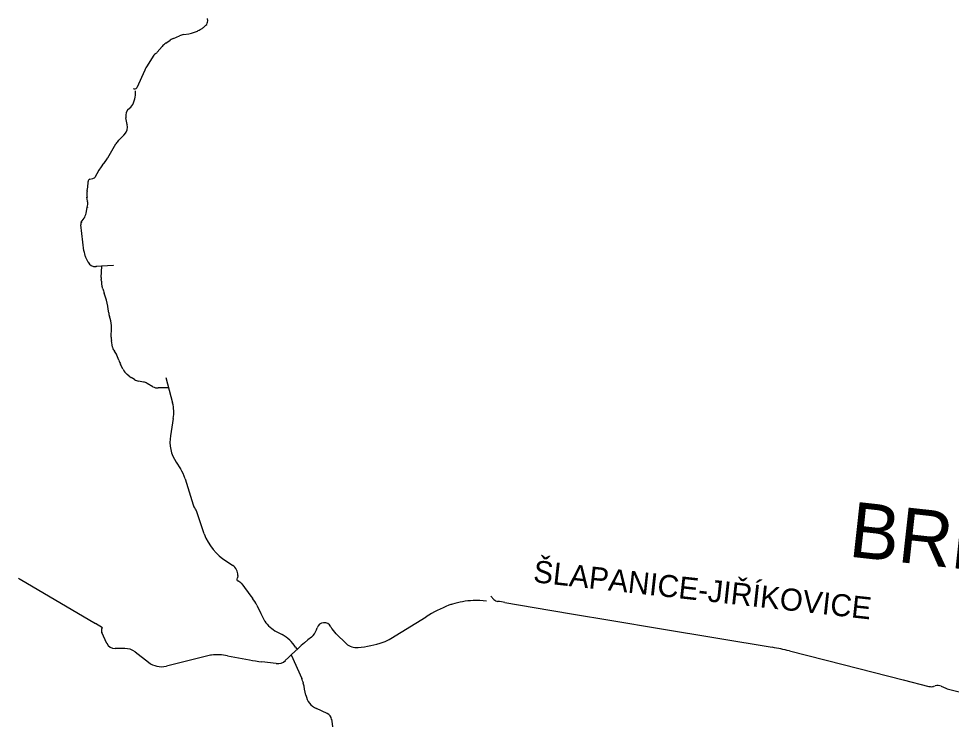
# Model space of a CAD drawing. Extents: x -678204 to -526855, y -1228851 to -1110393.
# Drawn here: x -590464 to -587930, y -1165121 to -1163218 of the extents above; entities that cross this region are included whole.
import ezdxf

# ---------------------------------------------------------------- set-up
doc = ezdxf.new("R2010")
doc.units = 0
for name, color, linetype in [('00_n_cyklo popisy detaily', 7, 'Continuous'), ('00_n_cyklo popisy ostatni', 7, 'Continuous'), ('00_n_cyklo realizace rekreacni vedlejsi', 7, 'Continuous'), ('00_n_cyklo studie rekreacni vedlejsi', 7, 'Continuous'), ('00_n_cyklo trasovani rekreacni vedlejsi', 7, 'Continuous')]:
    doc.layers.add(name, color=color, linetype=linetype)

msp = doc.modelspace()

# ---------------------------------------------------------------- linework, layer by layer
at = {"layer": '00_n_cyklo realizace rekreacni vedlejsi'}
for p, q in [((-590146.2, -1163416.5), (-590146.4, -1163413.8)), ((-590151.8, -1163446.5), (-590148.4, -1163435.5)), ((-590162.9, -1163461.8), (-590162.6, -1163461.6)), ((-590168.7, -1163505), (-590172.5, -1163487.1)), ((-590192.6, -1163548.5), (-590176.7, -1163532.2)), ((-590222, -1163595.9), (-590200, -1163558.2)), ((-590237.2, -1163616.9), (-590229.2, -1163606.4)), ((-590254.8, -1163646.5), (-590245.7, -1163629.9)), ((-590270.6, -1163654.3), (-590262.6, -1163652.4)), ((-590275.4, -1163666.7), (-590275.2, -1163660)), ((-590276.7, -1163713.3), (-590278.2, -1163703.2)), ((-590277.7, -1163685.9), (-590277.4, -1163684.4)), ((-590280.7, -1163746.5), (-590277.3, -1163731.2)), ((-590293.6, -1163771), (-590286.3, -1163759.9)), ((-590286.7, -1163848.9), (-590295.2, -1163777.7)), ((-590275.3, -1163878.9), (-590282.1, -1163864.6)), ((-590207.1, -1163887.9), (-590253.8, -1163891.4)), ((-590239.5, -1163921.3), (-590238.2, -1163890.2)), ((-590235.3, -1163951.4), (-590236.7, -1163945.2)), ((-590228.1, -1163974.1), (-590231.9, -1163963.5)), ((-590080, -1164220.5), (-590084.7, -1164220.9)), ((-590056.5, -1164220.8), (-590075.2, -1164220.4)), ((-589181.2, -1164786.7), (-589172.8, -1164795)), ((-589015.6, -1164825.3), (-588956.2, -1164835.4)), ((-588956.2, -1164835.4), (-588857.2, -1164851.5)), ((-588857.2, -1164851.5), (-588716.9, -1164874.7)), ((-588716.9, -1164874.7), (-588416.4, -1164925.2)), ((-588369.7, -1164934.9), (-588223.5, -1164971.5)), ((-588223.5, -1164971.5), (-588060.8, -1165013.5)), ((-588060.8, -1165013.5), (-587990.9, -1165031.3)), ((-587977.8, -1165031.1), (-587973.7, -1165029.9)), ((-587957.1, -1165030.9), (-587944.7, -1165036.2)), ((-587937.5, -1165038.6), (-587886.8, -1165051.5))]:
    msp.add_line(p, q, dxfattribs=at)
for points in [[(-590239.1, -1163930.6), (-590239.4, -1163926.5)], [(-590236.7, -1163945.2), (-590238.3, -1163937.2)], [(-590219.3, -1164017.1), (-590220.5, -1164006.7)], [(-590215.4, -1164032.3), (-590217.4, -1164026)], [(-590212.3, -1164082.5), (-590211.9, -1164057.4)], [(-590208.7, -1164110.3), (-590211.7, -1164091.6)], [(-590192, -1164145.2), (-590196.9, -1164131.6)], [(-590180.4, -1164170.1), (-590187.2, -1164156.5)], [(-590163.6, -1164188.8), (-590168.8, -1164184.6)], [(-590149.4, -1164198.3), (-590158.4, -1164192.6)], [(-590124.8, -1164204.8), (-590138.5, -1164202.4)], [(-590099.2, -1164217.5), (-590114.6, -1164208.5)], [(-589142.8, -1164803.6), (-589062.9, -1164817.4), (-589015.6, -1164825.3)]]:
    msp.add_lwpolyline(points, dxfattribs=at)
for centre in [(-590146.4, -1163413.8), (-590146.2, -1163416.5), (-590151.8, -1163446.5), (-590148.4, -1163435.5), (-590162.9, -1163461.8), (-590162.6, -1163461.6), (-590172.5, -1163487.1), (-590168.7, -1163505), (-590176.7, -1163532.2), (-590192.6, -1163548.5), (-590200, -1163558.2), (-590229.2, -1163606.4), (-590222, -1163595.9), (-590245.7, -1163629.9), (-590237.2, -1163616.9), (-590270.6, -1163654.3), (-590262.6, -1163652.4), (-590254.8, -1163646.5), (-590277.4, -1163684.4), (-590275.4, -1163666.7), (-590275.2, -1163660), (-590278.2, -1163703.2), (-590277.7, -1163685.9), (-590277.3, -1163731.2), (-590276.7, -1163713.3), (-590286.3, -1163759.9), (-590280.7, -1163746.5), (-590295.2, -1163777.7), (-590293.6, -1163771), (-590286.7, -1163848.9), (-590282.1, -1163864.6), (-590275.3, -1163878.9), (-590253.8, -1163891.4), (-590207.1, -1163887.9)]:
    msp.add_circle(centre, 0.15, dxfattribs=at)
for centre, radius, start, end in [((-590196, -1163420.4), 50, 342.4243, 4.5169), ((-590180.4, -1163437.4), 30, 306.4827, 342.4243), ((-590148.1, -1163481.9), 25, 126.4827, 191.9577), ((-590198.1, -1163511.2), 30, 315.5835, 11.9577), ((-590156.9, -1163583.4), 50, 135.5835, 149.6921), ((-590308.4, -1163545.4), 100, 322.3836, 329.6921), ((-590158, -1163677.9), 100, 142.3836, 151.2999), ((-590269.2, -1163660.1), 6, 103.1003, 178.6386), ((-590265.3, -1163640.7), 12, 283.1003, 331.2999), ((-590375.3, -1163664.3), 100, 348.4019, 358.6386), ((-590228.7, -1163696), 50, 168.4019, 188.347), ((-590326.2, -1163720.5), 50, 347.6706, 8.347), ((-590319.8, -1163738), 40, 326.7073, 347.6706), ((-590285.2, -1163776.5), 10, 146.7073, 186.7683), ((-590237, -1163843), 50, 186.7683, 205.6134), ((-590255.4, -1163869.4), 22, 205.6134, 274.1809), ((-590189.5, -1163923.3), 50, 177.6309, 183.6765), ((-590189.3, -1163927.4), 50, 183.6765, 191.2478), ((-590137.6, -1163930), 100, 192.3715, 199.5404), ((-590369.5, -1164024.3), 150, 6.7408, 19.5404), ((-590169.6, -1164011.2), 50, 186.7408, 197.1797), ((-590291.9, -1164055.9), 80, 358.9569, 17.1797), ((-590162.4, -1164083.4), 50, 178.9569, 189.4805), ((-590189, -1164107.2), 20, 188.9564, 223.6965), ((-590225.1, -1164141.7), 30, 19.6706, 43.6965), ((-590097.8, -1164111.6), 100, 199.6706, 206.6907), ((-590140.1, -1164149.9), 45, 206.6907, 230.4758), ((-590131.8, -1164150.3), 50, 230.4758, 237.866), ((-590133.4, -1164172.9), 30, 237.866, 260.3649), ((-590129.8, -1164234.3), 30, 59.6272, 80.3649), ((-590086.6, -1164195.9), 25, 239.6272, 274.3125), ((-590076.3, -1164270.4), 50, 88.7974, 94.3125), ((-589158.8, -1164780.7), 20, 225.5225, 260.9876), ((-589379.8, -1166174.2), 1391, 80.1867, 80.9876), ((-588516.4, -1165521.1), 604.3, 75.9478, 80.4704), ((-587984.7, -1165007.1), 25, 255.7386, 285.9313), ((-587966.8, -1165054), 25, 67.0256, 105.9313), ((-587925.2, -1164990.2), 50, 247.0256, 255.7206)]:
    msp.add_arc(centre, radius, start, end, dxfattribs=at)
at = {"layer": '00_n_cyklo studie rekreacni vedlejsi'}
for p, q in [((-590098.4, -1163320), (-590114.9, -1163345.9)), ((-590121.4, -1163357.9), (-590143.2, -1163405.6)), ((-590063.8, -1164192.7), (-590045.7, -1164261.7)), ((-590043.8, -1164303.6), (-590051.6, -1164350.5)), ((-590035.9, -1164422.7), (-590024.3, -1164440.1)), ((-590011.5, -1164467.2), (-589990.1, -1164538.6)), ((-589959.6, -1164617.3), (-589979.5, -1164557.2)), ((-589898.9, -1164691.5), (-589882.1, -1164702.6)), ((-590459.5, -1164740.4), (-590254.9, -1164860.8)), ((-589868.8, -1164729.9), (-589869.2, -1164736.1)), ((-589452.2, -1164901.2), (-589356.6, -1164842)), ((-589654.6, -1164877.6), (-589652.8, -1164872)), ((-590224.6, -1164914.4), (-590238, -1164884.8)), ((-589601.6, -1164888.7), (-589573.6, -1164915.2)), ((-590175.6, -1164928.3), (-590201.6, -1164928.7)), ((-590147.3, -1164937.8), (-590111.4, -1164965.8)), ((-589946.5, -1164947.4), (-590062.6, -1164976.2)), ((-589896.4, -1164948.1), (-589836.9, -1164959.4)), ((-589723.7, -1164945.7), (-589694.8, -1165009.8)), ((-589763.9, -1164969.4), (-589802.9, -1164964.7)), ((-589625.2, -1165105.1), (-589654.9, -1165091.7)), ((-589613.6, -1165120.7), (-589602.2, -1165208.7))]:
    msp.add_line(p, q, dxfattribs=at)
for points in [[(-589950.2, -1163224.2), (-589950.5, -1163218)], [(-589993.9, -1163257), (-589981, -1163252.8)], [(-589970.6, -1163247.9), (-589967.1, -1163245.7)], [(-589959.7, -1163240.2), (-589955.1, -1163236)], [(-590064.1, -1163284.7), (-590052, -1163276.4)], [(-590043.5, -1163271.7), (-590026.9, -1163264.6)], [(-590015.3, -1163261.2), (-590001.6, -1163258.9)], [(-590087.1, -1163309.1), (-590074, -1163293.6)], [(-589870.5, -1164744.1), (-589868.8, -1164744.8)], [(-589857.8, -1164753.1), (-589832.9, -1164786), (-589828.7, -1164791.3)], [(-589817, -1164810.4), (-589806.2, -1164833.6), (-589796.1, -1164853.2), (-589795.4, -1164854.2)], [(-590236.4, -1164872.4), (-590254.9, -1164860.8)], [(-590237.5, -1164874), (-590236.6, -1164872.4)], [(-589762.7, -1164882.7), (-589747.8, -1164890.8)], [(-589711.5, -1164924.6), (-589707.4, -1164930.9)]]:
    msp.add_lwpolyline(points, dxfattribs=at)
for centre, radius, start, end in [((-589965.2, -1163224.9), 15, 312.1361, 2.6801), ((-589996.9, -1163205.3), 50, 288.4339, 301.6564), ((-589993.3, -1163203.1), 50, 301.6564, 312.1361), ((-590023.7, -1163317.6), 50, 113.2231, 124.4406), ((-590007.2, -1163310.5), 50, 99.2944, 113.2231), ((-590009.7, -1163209.6), 50, 279.2944, 288.4339), ((-590035.8, -1163325.9), 50, 124.4406, 139.8304), ((-590077.3, -1163333.3), 25, 120.6685, 147.6354), ((-590077.3, -1163333.3), 25, 120.6685, 147.6354), ((-590095.2, -1163303.2), 10, 300.6685, 323.9419), ((-590095.2, -1163303.2), 10, 300.6685, 323.9419), ((-590030.4, -1163399.5), 100, 147.6354, 155.4273), ((-590148.6, -1163403.1), 6, 225.4297, 335.4273), ((-590142.4, -1164287.1), 100, 350.5356, 14.7447), ((-589952.9, -1164366.9), 100, 170.5356, 213.8978), ((-590107.3, -1164495.8), 100, 16.6191, 33.8978), ((-589966.2, -1164531.4), 25, 196.6191, 222.2199), ((-590003.2, -1164565), 25, 18.2973, 42.2199), ((-589822.6, -1164567), 146, 200.1716, 238.4923), ((-589898.7, -1164727.6), 30, 355.6339, 56.3797), ((-590307.3, -1164481.9), 300, 238.5446, 239.5198), ((-589919.1, -1164732.3), 50, 346.3064, 355.6339), ((-589877.7, -1164768.2), 25, 37.1498, 69.0418), ((-589907.6, -1164852.7), 100, 25.0255, 37.8767), ((-589213.5, -1165056.5), 258.9, 93.4939, 106.102), ((-589219, -1164966.4), 168.6, 81.0643, 93.4939), ((-589150.3, -1165175.8), 392.4, 111.6047, 121.7233), ((-589256.7, -1164907), 103.2, 106.102, 111.6047), ((-590227.1, -1164879.9), 12, 150.5926, 204.4551), ((-589714.9, -1164794.9), 100, 216.3799, 241.4344), ((-589633.8, -1164878.2), 20, 26.0341, 161.771), ((-589555.8, -1164840.1), 66.8, 206.0341, 226.6447), ((-589795.6, -1164978.6), 100, 32.7381, 61.4344), ((-589073.1, -1165635.3), 948, 128.9123, 134.6494), ((-589695.6, -1164864.1), 43.2, 308.9123, 341.771), ((-590201.9, -1164903.7), 25, 205.1649, 270.8368), ((-589546.2, -1164886.1), 40, 226.6447, 276.2436), ((-589578.5, -1164590), 337.9, 276.2436, 288.0598), ((-589504.8, -1164816.1), 100, 288.0598, 301.7233), ((-590175, -1164973.3), 45, 52.0977, 90.8368), ((-589934.5, -1164996), 50, 95.8026, 103.9123), ((-589924.4, -1165095.5), 150, 79.2195, 95.8026), ((-590076.3, -1164920.9), 57, 232.0977, 283.9123), ((-589743.4, -1164468.2), 500, 259.2195, 263.1725), ((-589760.3, -1164939.6), 30, 263.1725, 314.6494), ((-589763.2, -1165040.6), 75, 13.8355, 24.2148), ((-590170.8, -1165141), 494.7, 10.0265, 13.8355), ((-589634.4, -1165046.1), 50, 190.0265, 245.8094), ((-589633.4, -1165123.3), 20, 7.3592, 65.8094)]:
    msp.add_arc(centre, radius, start, end, dxfattribs=at)
at = {"layer": '00_n_cyklo trasovani rekreacni vedlejsi'}
for p, q in [((-590098.4, -1163320), (-590114.9, -1163345.9)), ((-590121.4, -1163357.9), (-590143.2, -1163405.6)), ((-590146.2, -1163416.5), (-590146.4, -1163413.8)), ((-590151.8, -1163446.5), (-590148.4, -1163435.5)), ((-590162.9, -1163461.8), (-590162.6, -1163461.6)), ((-590168.7, -1163505), (-590172.5, -1163487.1)), ((-590192.6, -1163548.5), (-590176.7, -1163532.2)), ((-590222, -1163595.9), (-590200, -1163558.2)), ((-590237.2, -1163616.9), (-590229.2, -1163606.4)), ((-590254.8, -1163646.5), (-590245.7, -1163629.9)), ((-590270.6, -1163654.3), (-590262.6, -1163652.4)), ((-590275.4, -1163666.7), (-590275.2, -1163660)), ((-590276.7, -1163713.3), (-590278.2, -1163703.2)), ((-590277.7, -1163685.9), (-590277.4, -1163684.4)), ((-590280.7, -1163746.5), (-590277.3, -1163731.2)), ((-590293.6, -1163771), (-590286.3, -1163759.9)), ((-590286.7, -1163848.9), (-590295.2, -1163777.7)), ((-590275.3, -1163878.9), (-590282.1, -1163864.6)), ((-590207.1, -1163887.9), (-590253.8, -1163891.4)), ((-590239.5, -1163921.3), (-590238.2, -1163890.2)), ((-590235.3, -1163951.4), (-590236.7, -1163945.2)), ((-590228.1, -1163974.1), (-590231.9, -1163963.5)), ((-590063.8, -1164192.7), (-590045.7, -1164261.7)), ((-590080, -1164220.5), (-590084.7, -1164220.9)), ((-590056.5, -1164220.8), (-590075.2, -1164220.4)), ((-590043.8, -1164303.6), (-590051.6, -1164350.5)), ((-590035.9, -1164422.7), (-590024.3, -1164440.1)), ((-590011.5, -1164467.2), (-589990.1, -1164538.6)), ((-589959.6, -1164617.3), (-589979.5, -1164557.2)), ((-589898.9, -1164691.5), (-589882.1, -1164702.6)), ((-590459.5, -1164740.4), (-590254.9, -1164860.8)), ((-589868.8, -1164729.9), (-589869.2, -1164736.1)), ((-589181.2, -1164786.7), (-589172.8, -1164795)), ((-589452.2, -1164901.2), (-589356.6, -1164842)), ((-589015.6, -1164825.3), (-588956.2, -1164835.4)), ((-588956.2, -1164835.4), (-588857.2, -1164851.5)), ((-589654.6, -1164877.6), (-589652.8, -1164872)), ((-588857.2, -1164851.5), (-588716.9, -1164874.7)), ((-588716.9, -1164874.7), (-588416.4, -1164925.2)), ((-590224.6, -1164914.4), (-590238, -1164884.8)), ((-589601.6, -1164888.7), (-589573.6, -1164915.2)), ((-590175.6, -1164928.3), (-590201.6, -1164928.7)), ((-590147.3, -1164937.8), (-590111.4, -1164965.8)), ((-589946.5, -1164947.4), (-590062.6, -1164976.2)), ((-589896.4, -1164948.1), (-589836.9, -1164959.4)), ((-589723.7, -1164945.7), (-589694.8, -1165009.8)), ((-588369.7, -1164934.9), (-588223.5, -1164971.5)), ((-589763.9, -1164969.4), (-589802.9, -1164964.7)), ((-588223.5, -1164971.5), (-588060.8, -1165013.5)), ((-588060.8, -1165013.5), (-587990.9, -1165031.3)), ((-587977.8, -1165031.1), (-587973.7, -1165029.9)), ((-587957.1, -1165030.9), (-587944.7, -1165036.2)), ((-587937.5, -1165038.6), (-587886.8, -1165051.5)), ((-589625.2, -1165105.1), (-589654.9, -1165091.7)), ((-589613.6, -1165120.7), (-589602.2, -1165208.7))]:
    msp.add_line(p, q, dxfattribs=at)
for points in [[(-589950.2, -1163224.2), (-589950.5, -1163218)], [(-589993.9, -1163257), (-589981, -1163252.8)], [(-589970.6, -1163247.9), (-589967.1, -1163245.7)], [(-589959.7, -1163240.2), (-589955.1, -1163236)], [(-590064.1, -1163284.7), (-590052, -1163276.4)], [(-590043.5, -1163271.7), (-590026.9, -1163264.6)], [(-590015.3, -1163261.2), (-590001.6, -1163258.9)], [(-590087.1, -1163309.1), (-590074, -1163293.6)], [(-590239.1, -1163930.6), (-590239.4, -1163926.5)], [(-590236.7, -1163945.2), (-590238.3, -1163937.2)], [(-590219.3, -1164017.1), (-590220.5, -1164006.7)], [(-590215.4, -1164032.3), (-590217.4, -1164026)], [(-590212.3, -1164082.5), (-590211.9, -1164057.4)], [(-590208.7, -1164110.3), (-590211.7, -1164091.6)], [(-590192, -1164145.2), (-590196.9, -1164131.6)], [(-590180.4, -1164170.1), (-590187.2, -1164156.5)], [(-590163.6, -1164188.8), (-590168.8, -1164184.6)], [(-590149.4, -1164198.3), (-590158.4, -1164192.6)], [(-590124.8, -1164204.8), (-590138.5, -1164202.4)], [(-590099.2, -1164217.5), (-590114.6, -1164208.5)], [(-589870.5, -1164744.1), (-589868.8, -1164744.8)], [(-589857.8, -1164753.1), (-589832.9, -1164786), (-589828.7, -1164791.3)], [(-589817, -1164810.4), (-589806.2, -1164833.6), (-589796.1, -1164853.2), (-589795.4, -1164854.2)], [(-589142.8, -1164803.6), (-589062.9, -1164817.4), (-589015.6, -1164825.3)], [(-590236.4, -1164872.4), (-590254.9, -1164860.8)], [(-590237.5, -1164874), (-590236.6, -1164872.4)], [(-589762.7, -1164882.7), (-589747.8, -1164890.8)], [(-589711.5, -1164924.6), (-589707.4, -1164930.9)]]:
    msp.add_lwpolyline(points, dxfattribs=at)
for centre in [(-590146.4, -1163413.8), (-590146.2, -1163416.5), (-590151.8, -1163446.5), (-590148.4, -1163435.5), (-590162.9, -1163461.8), (-590162.6, -1163461.6), (-590172.5, -1163487.1), (-590168.7, -1163505), (-590176.7, -1163532.2), (-590192.6, -1163548.5), (-590200, -1163558.2), (-590229.2, -1163606.4), (-590222, -1163595.9), (-590245.7, -1163629.9), (-590237.2, -1163616.9), (-590270.6, -1163654.3), (-590262.6, -1163652.4), (-590254.8, -1163646.5), (-590277.4, -1163684.4), (-590275.4, -1163666.7), (-590275.2, -1163660), (-590278.2, -1163703.2), (-590277.7, -1163685.9), (-590277.3, -1163731.2), (-590276.7, -1163713.3), (-590286.3, -1163759.9), (-590280.7, -1163746.5), (-590295.2, -1163777.7), (-590293.6, -1163771), (-590286.7, -1163848.9), (-590282.1, -1163864.6), (-590275.3, -1163878.9), (-590253.8, -1163891.4), (-590207.1, -1163887.9)]:
    msp.add_circle(centre, 0.15, dxfattribs=at)
for centre, radius, start, end in [((-589965.2, -1163224.9), 15, 312.1361, 2.6801), ((-589996.9, -1163205.3), 50, 288.4339, 301.6564), ((-589993.3, -1163203.1), 50, 301.6564, 312.1361), ((-590023.7, -1163317.6), 50, 113.2231, 124.4406), ((-590007.2, -1163310.5), 50, 99.2944, 113.2231), ((-590009.7, -1163209.6), 50, 279.2944, 288.4339), ((-590035.8, -1163325.9), 50, 124.4406, 139.8304), ((-590077.3, -1163333.3), 25, 120.6685, 147.6354), ((-590077.3, -1163333.3), 25, 120.6685, 147.6354), ((-590095.2, -1163303.2), 10, 300.6685, 323.9419), ((-590095.2, -1163303.2), 10, 300.6685, 323.9419), ((-590030.4, -1163399.5), 100, 147.6354, 155.4273), ((-590148.6, -1163403.1), 6, 225.4297, 335.4273), ((-590196, -1163420.4), 50, 342.4243, 4.5169), ((-590180.4, -1163437.4), 30, 306.4827, 342.4243), ((-590148.1, -1163481.9), 25, 126.4827, 191.9577), ((-590198.1, -1163511.2), 30, 315.5835, 11.9577), ((-590156.9, -1163583.4), 50, 135.5835, 149.6921), ((-590308.4, -1163545.4), 100, 322.3836, 329.6921), ((-590158, -1163677.9), 100, 142.3836, 151.2999), ((-590269.2, -1163660.1), 6, 103.1003, 178.6386), ((-590265.3, -1163640.7), 12, 283.1003, 331.2999), ((-590375.3, -1163664.3), 100, 348.4019, 358.6386), ((-590228.7, -1163696), 50, 168.4019, 188.347), ((-590326.2, -1163720.5), 50, 347.6706, 8.347), ((-590319.8, -1163738), 40, 326.7073, 347.6706), ((-590285.2, -1163776.5), 10, 146.7073, 186.7683), ((-590237, -1163843), 50, 186.7683, 205.6134), ((-590255.4, -1163869.4), 22, 205.6134, 274.1809), ((-590189.5, -1163923.3), 50, 177.6309, 183.6765), ((-590189.3, -1163927.4), 50, 183.6765, 191.2478), ((-590137.6, -1163930), 100, 192.3715, 199.5404), ((-590369.5, -1164024.3), 150, 6.7408, 19.5404), ((-590169.6, -1164011.2), 50, 186.7408, 197.1797), ((-590291.9, -1164055.9), 80, 358.9569, 17.1797), ((-590162.4, -1164083.4), 50, 178.9569, 189.4805), ((-590189, -1164107.2), 20, 188.9564, 223.6965), ((-590225.1, -1164141.7), 30, 19.6706, 43.6965), ((-590097.8, -1164111.6), 100, 199.6706, 206.6907), ((-590140.1, -1164149.9), 45, 206.6907, 230.4758), ((-590131.8, -1164150.3), 50, 230.4758, 237.866), ((-590133.4, -1164172.9), 30, 237.866, 260.3649), ((-590129.8, -1164234.3), 30, 59.6272, 80.3649), ((-590086.6, -1164195.9), 25, 239.6272, 274.3125), ((-590076.3, -1164270.4), 50, 88.7974, 94.3125), ((-590142.4, -1164287.1), 100, 350.5356, 14.7447), ((-589952.9, -1164366.9), 100, 170.5356, 213.8978), ((-590107.3, -1164495.8), 100, 16.6191, 33.8978), ((-589966.2, -1164531.4), 25, 196.6191, 222.2199), ((-590003.2, -1164565), 25, 18.2973, 42.2199), ((-589822.6, -1164567), 146, 200.1716, 238.4923), ((-589898.7, -1164727.6), 30, 355.6339, 56.3797), ((-590307.3, -1164481.9), 300, 238.5446, 239.5198), ((-589919.1, -1164732.3), 50, 346.3064, 355.6339), ((-589877.7, -1164768.2), 25, 37.1498, 69.0418), ((-589907.6, -1164852.7), 100, 25.0255, 37.8767), ((-589213.5, -1165056.5), 258.9, 93.4939, 106.102), ((-589219, -1164966.4), 168.6, 81.0643, 93.4939), ((-589158.8, -1164780.7), 20, 225.5225, 260.9876), ((-589150.3, -1165175.8), 392.4, 111.6047, 121.7233), ((-589256.7, -1164907), 103.2, 106.102, 111.6047), ((-589379.8, -1166174.2), 1391, 80.1867, 80.9876), ((-590227.1, -1164879.9), 12, 150.5926, 204.4551), ((-589714.9, -1164794.9), 100, 216.3799, 241.4344), ((-589633.8, -1164878.2), 20, 26.0341, 161.771), ((-589555.8, -1164840.1), 66.8, 206.0341, 226.6447), ((-589795.6, -1164978.6), 100, 32.7381, 61.4344), ((-589073.1, -1165635.3), 948, 128.9123, 134.6494), ((-589695.6, -1164864.1), 43.2, 308.9123, 341.771), ((-590201.9, -1164903.7), 25, 205.1649, 270.8368), ((-589546.2, -1164886.1), 40, 226.6447, 276.2436), ((-589578.5, -1164590), 337.9, 276.2436, 288.0598), ((-589504.8, -1164816.1), 100, 288.0598, 301.7233), ((-588516.4, -1165521.1), 604.3, 75.9478, 80.4704), ((-590175, -1164973.3), 45, 52.0977, 90.8368), ((-589934.5, -1164996), 50, 95.8026, 103.9123), ((-589924.4, -1165095.5), 150, 79.2195, 95.8026), ((-590076.3, -1164920.9), 57, 232.0977, 283.9123), ((-589743.4, -1164468.2), 500, 259.2195, 263.1725), ((-589760.3, -1164939.6), 30, 263.1725, 314.6494), ((-589763.2, -1165040.6), 75, 13.8355, 24.2148), ((-590170.8, -1165141), 494.7, 10.0265, 13.8355), ((-587984.7, -1165007.1), 25, 255.7386, 285.9313), ((-587966.8, -1165054), 25, 67.0256, 105.9313), ((-587925.2, -1164990.2), 50, 247.0256, 255.7206), ((-589634.4, -1165046.1), 50, 190.0265, 245.8094), ((-589633.4, -1165123.3), 20, 7.3592, 65.8094)]:
    msp.add_arc(centre, radius, start, end, dxfattribs=at)

# ---------------------------------------------------------------- texts
at = {"layer": '00_n_cyklo popisy detaily'}
msp.add_text('ŠLAPANICE-JIŘÍKOVICE', height=60, rotation=353.6836, dxfattribs=at).set_placement((-589067.6, -1164748))
msp.add_text('ŠLAPANICE-JIŘÍKOVICE', height=60, rotation=353.6836, dxfattribs=at).set_placement((-589067.6, -1164748))
msp.add_text('ŠLAPANICE-JIŘÍKOVICE', height=60, rotation=353.6836, dxfattribs=at).set_placement((-589067.6, -1164748))
at = {"layer": '00_n_cyklo popisy ostatni'}
msp.add_text('BRNO-SLAVKOV', height=150, rotation=353.6836, dxfattribs=at).set_placement((-588211.6, -1164678.3))

doc.saveas('drawing.dxf')
